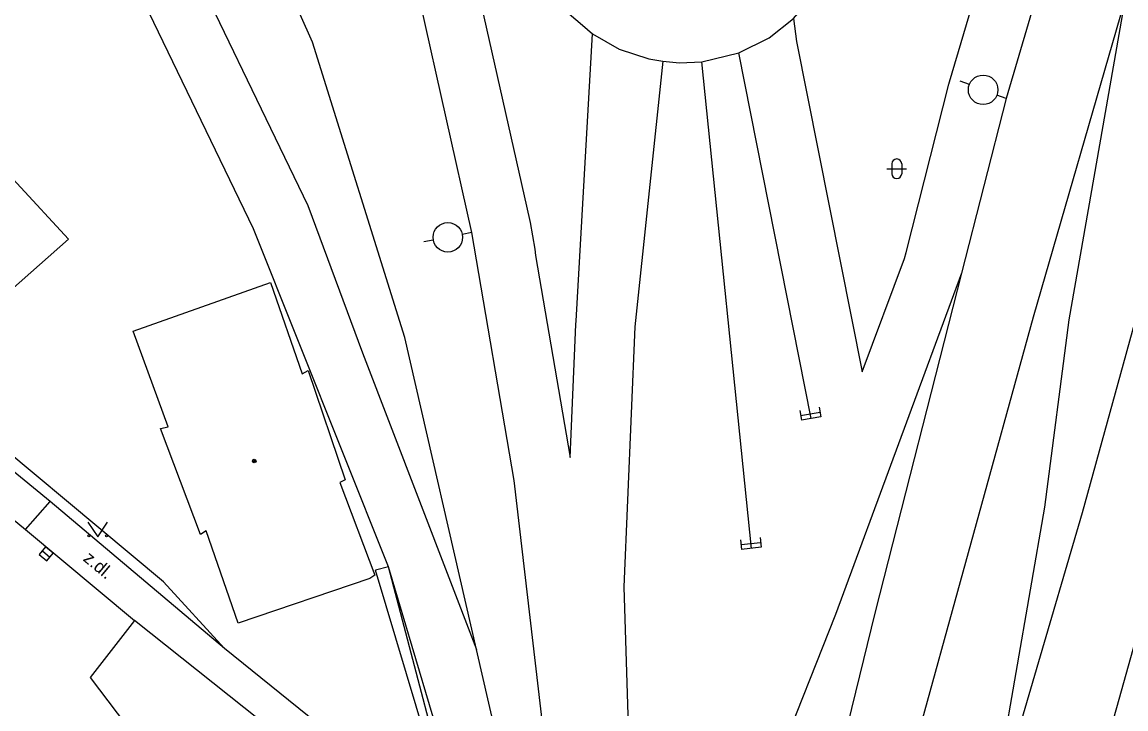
# Model space of a CAD drawing. Extents: x -598932 to -598196, y -1162207 to -1161504.
# Drawn here: x -598384.6 to -598328.5, y -1161967.1 to -1161932.2 of the extents above; entities that cross this region are included whole.
import ezdxf

# ---------------------------------------------------------------- set-up
doc = ezdxf.new("R2010")
doc.units = 0
for name, color, linetype in [('Level 12', 7, 'Continuous'), ('Level 27', 7, 'Continuous'), ('Level 36', 7, 'Continuous'), ('Level 39', 7, 'Continuous'), ('TM - budovy zdene_ betonove - VP', 7, 'Continuous'), ('TM - CD - osa koleji', 7, 'Continuous'), ('TM - chodniky - VP', 7, 'Continuous'), ('TM - komunikace - VP', 7, 'Continuous'), ('TM - letecke snimky - pomocna linie', 7, 'Continuous'), ('TM - plot zdeny_ ohradni zed - VP', 7, 'Continuous'), ('TM - popis povrchu', 7, 'Continuous'), ('TM - rozhrani mezi zpev. plochami mezi sebou - VP', 7, 'Continuous'), ('TM - rozhrani ploch obecne - VP', 7, 'Continuous')]:
    doc.layers.add(name, color=color, linetype=linetype)

msp = doc.modelspace()

# ---------------------------------------------------------------- linework, layer by layer
at = {"layer": 'Level 12'}
for p, q in [((-598336.446, -1161935.361), (-598336.913, -1161935.182)), ((-598334.58, -1161936.08), (-598335.047, -1161935.9)), ((-598361.74, -1161942.89), (-598362.231, -1161942.986)), ((-598363.703, -1161943.273), (-598364.194, -1161943.369)), ((-598345.066, -1161951.94), (-598344.983, -1161952.433)), ((-598345.025, -1161952.187), (-598344.039, -1161952.02)), ((-598344.08, -1161951.774), (-598343.997, -1161952.267)), ((-598343.997, -1161952.267), (-598344.983, -1161952.433)), ((-598348.084, -1161958.51), (-598348.027, -1161959.007)), ((-598348.055, -1161958.759), (-598347.062, -1161958.645)), ((-598347.033, -1161958.893), (-598348.027, -1161959.007)), ((-598347.09, -1161958.396), (-598347.033, -1161958.893))]:
    msp.add_line(p, q, dxfattribs=at)
for centre in [(-598335.747, -1161935.631), (-598362.967, -1161943.13)]:
    msp.add_circle(centre, 0.75, dxfattribs=at)
at = {"layer": 'Level 27'}
msp.add_line((-598383.583, -1161959.071), (-598383.197, -1161959.389), dxfattribs=at)
msp.add_lwpolyline([(-598383.742, -1161959.263), (-598383.357, -1161959.582), (-598383.038, -1161959.197), (-598383.423, -1161958.878)], close=True, dxfattribs=at)
at = {"layer": 'Level 36'}
for p, q in [((-598340.636, -1161939.646), (-598339.636, -1161939.646)), ((-598340.386, -1161939.396), (-598340.386, -1161939.896)), ((-598339.886, -1161939.396), (-598339.886, -1161939.896))]:
    msp.add_line(p, q, dxfattribs=at)
msp.add_lwpolyline([(-598381.27, -1161957.61), (-598380.77, -1161958.36), (-598380.27, -1161957.61)], dxfattribs=at)
for centre in [(-598381.22, -1161958.31), (-598380.321, -1161958.31)]:
    msp.add_circle(centre, 0.05, dxfattribs=at)
for centre, start, end in [((-598340.136, -1161939.396), 0, 180), ((-598340.136, -1161939.896), 180, 0)]:
    msp.add_arc(centre, 0.25, start, end, dxfattribs=at)
at = {"layer": 'Level 39'}
for radius in [0.09, 0.0398]:
    msp.add_circle((-598372.81, -1161954.51), radius, dxfattribs=at)
at = {"layer": 'TM - budovy zdene_ betonove - VP'}
for points in [[(-598387.52, -1161937.53), (-598382.26, -1161943.22)], [(-598382.26, -1161943.22), (-598389.64, -1161949.76)], [(-598378.97, -1161947.9), (-598371.98, -1161945.43)], [(-598371.98, -1161945.43), (-598370.38, -1161950.07)], [(-598377.19, -1161952.77), (-598378.97, -1161947.9)], [(-598370.38, -1161950.07), (-598370.06, -1161949.9)], [(-598370.06, -1161949.9), (-598368.18, -1161955.46)], [(-598377.57, -1161952.85), (-598377.19, -1161952.77)], [(-598375.55, -1161958.25), (-598377.57, -1161952.85)], [(-598368.18, -1161955.46), (-598368.46, -1161955.6)], [(-598368.46, -1161955.6), (-598366.68, -1161960.32)], [(-598375.25, -1161958.06), (-598375.55, -1161958.25)], [(-598373.63, -1161962.75), (-598375.25, -1161958.06)], [(-598366.94, -1161960.48), (-598373.63, -1161962.75)], [(-598366.68, -1161960.32), (-598366.94, -1161960.48)]]:
    msp.add_lwpolyline(points, dxfattribs=at)
at = {"layer": 'TM - CD - osa koleji'}
for points in [[(-598357.12, -1161977.93), (-598357.69, -1161971.76), (-598359.59, -1161955.49), (-598361.74, -1161942.89), (-598364.36, -1161931.22), (-598367.93, -1161915.3), (-598369.9, -1161906.65), (-598373.89, -1161889.05), (-598376.8, -1161873.73), (-598378.32, -1161860.94), (-598378.07, -1161843.25), (-598377.06, -1161830.11), (-598374.53, -1161806.47), (-598368.34, -1161750.33)], [(-598330.7, -1161957.12), (-598323.25, -1161930.13), (-598318.14, -1161914.72), (-598309.03, -1161890.52), (-598298.97, -1161868.44), (-598286, -1161841.52), (-598259.79, -1161788.26), (-598258.34, -1161785.34)], [(-598253.85, -1161787.55), (-598277.35, -1161835.24), (-598288.92, -1161858.05), (-598298.17, -1161877.98), (-598306.86, -1161898.82), (-598315.14, -1161920.44), (-598321.21, -1161940.59), (-598327.42, -1161961.55), (-598336.66, -1161994.53)], [(-598358.6, -1161976.73), (-598359.33, -1161973.53), (-598361.51, -1161964.09), (-598365.16, -1161948.23), (-598369.84, -1161933.2), (-598376.68, -1161917.87), (-598383.52, -1161906), (-598391.62, -1161893.76), (-598407.56, -1161871.85), (-598439.71, -1161827.1)], [(-598443.51, -1161830.07), (-598393.48, -1161900.03), (-598385.66, -1161911.94), (-598377.18, -1161926.79), (-598370.08, -1161941.52), (-598367.3, -1161949), (-598361.51, -1161964.09)], [(-598344.63, -1161988.07), (-598339.52, -1161970.16), (-598333.18, -1161947.17), (-598328.56, -1161931.17), (-598325.59, -1161920.89), (-598322.72, -1161911.41)], [(-598327.42, -1161911.8), (-598331.69, -1161926.28), (-598334.58, -1161936.08), (-598336.84, -1161944.95), (-598341.23, -1161962.18)], [(-598328.56, -1161931.17), (-598331.39, -1161947.33), (-598332.63, -1161956.86)], [(-598352.04, -1161934.18), (-598353.46, -1161947.69), (-598354.02, -1161960.9), (-598353.6, -1161974.49), (-598353.52, -1161980.85)], [(-598347.53, -1161958.95), (-598350.05, -1161934.2)], [(-598344.49, -1161952.35), (-598348.17, -1161933.75)], [(-598336.84, -1161944.95), (-598343.26, -1161962.31), (-598349.19, -1161977.3)], [(-598340.66, -1161991.29), (-598335.54, -1161973.67), (-598330.7, -1161957.12)], [(-598332.63, -1161956.86), (-598335.54, -1161973.67), (-598338.76, -1161992.83)], [(-598341.23, -1161962.18), (-598345.04, -1161977.69), (-598346.87, -1161986.25)]]:
    msp.add_lwpolyline(points, dxfattribs=at)
at = {"layer": 'TM - chodniky - VP'}
for points in [[(-598383.18, -1161956.56), (-598389.24, -1161951.61), (-598388.84, -1161951.12)], [(-598374.33, -1161964.05), (-598383.18, -1161956.56)], [(-598372.08, -1161978.94), (-598362.72, -1161975.49), (-598362.959, -1161975.299), (-598378.9, -1161962.61)]]:
    msp.add_lwpolyline(points, dxfattribs=at)
at = {"layer": 'TM - komunikace - VP'}
for points in [[(-598397.6, -1161947.15), (-598384.44, -1161957.99)], [(-598384.44, -1161957.99), (-598378.9, -1161962.61)], [(-598378.9, -1161962.61), (-598381.15, -1161965.52)], [(-598381.15, -1161965.52), (-598378.88, -1161968.52), (-598377.41, -1161970.94), (-598376.54, -1161972.52), (-598374.95, -1161975.07), (-598373.56, -1161977.04), (-598372.08, -1161978.94)]]:
    msp.add_lwpolyline(points, dxfattribs=at)
at = {"layer": 'TM - letecke snimky - pomocna linie'}
for points in [[(-598358.5, -1161739.6), (-598360.13, -1161751.92), (-598365.72, -1161802.62), (-598368.75, -1161829.91), (-598369.16, -1161834.56), (-598370.51, -1161850.29), (-598370.51, -1161867.69), (-598369, -1161887.95), (-598366.97, -1161905.98), (-598366.91, -1161906.31), (-598365, -1161914.64), (-598361.52, -1161930.21), (-598361.44, -1161930.56), (-598361.4, -1161930.7), (-598358.81, -1161942.23), (-598358.78, -1161942.38), (-598358.55, -1161943.74), (-598358.5, -1161944.06), (-598356.74, -1161954.33), (-598356.46, -1161947.56), (-598356.44, -1161947.38), (-598355.61, -1161932.79)], [(-598345.39, -1161932), (-598345.23, -1161933.17), (-598341.9, -1161949.98), (-598339.75, -1161944.21), (-598339.66, -1161943.91), (-598337.49, -1161935.34), (-598337.46, -1161935.23), (-598334.67, -1161925.84), (-598334.58, -1161925.43), (-598332.32, -1161909.94), (-598332.3, -1161909.85), (-598330.27, -1161898.83), (-598330.22, -1161898.47), (-598329.83, -1161891.84), (-598329.69, -1161889.41), (-598329.17, -1161880.36), (-598328.79, -1161864.7), (-598328.78, -1161864.55), (-598327.89, -1161852.55), (-598327.88, -1161852.43), (-598323.84, -1161817.24), (-598322.85, -1161808.11), (-598322.82, -1161807.86), (-598319.23, -1161762.27)], [(-598365.98, -1161959.89), (-598372.84, -1161942.7), (-598379.84, -1161928.19), (-598388.22, -1161913.51), (-598395.95, -1161901.73), (-598401.88, -1161893.44), (-598433.5, -1161849.22), (-598433.36, -1161849.42), (-598434.44, -1161847.92), (-598445.72, -1161833.26), (-598448.77, -1161829.32)]]:
    msp.add_lwpolyline(points, dxfattribs=at)
at = {"layer": 'TM - plot zdeny_ ohradni zed - VP'}
for points in [[(-598374.33, -1161964.05), (-598377.42, -1161960.65), (-598388.84, -1161951.12)], [(-598363.5, -1161972.77), (-598374.33, -1161964.05)]]:
    msp.add_lwpolyline(points, dxfattribs=at)
at = {"layer": 'TM - rozhrani mezi zpev. plochami mezi sebou - VP'}
msp.add_lwpolyline([(-598384.44, -1161957.99), (-598383.18, -1161956.56)], dxfattribs=at)
at = {"layer": 'TM - rozhrani ploch obecne - VP'}
for points in [[(-598348.17, -1161933.75), (-598346.63, -1161932.98), (-598345.39, -1161932), (-598344.38, -1161930.81), (-598343.61, -1161929.43), (-598343.12, -1161927.94), (-598342.93, -1161926.38), (-598343.05, -1161924.81), (-598343.48, -1161923.3), (-598344.19, -1161921.89), (-598345.16, -1161920.65), (-598346.35, -1161919.63), (-598347.71, -1161918.85), (-598348.32, -1161918.61), (-598349.21, -1161918.36), (-598350.29, -1161918.19), (-598351.3, -1161918.12), (-598352.19, -1161918.25), (-598353.83, -1161918.68)], [(-598353.83, -1161918.68), (-598355.33, -1161919.43), (-598356.56, -1161920.41), (-598357.58, -1161921.61), (-598358.35, -1161922.98), (-598358.84, -1161924.47), (-598359.02, -1161926.03), (-598358.91, -1161927.6), (-598358.48, -1161929.12), (-598357.77, -1161930.52), (-598356.8, -1161931.76), (-598356.12, -1161932.35), (-598355.61, -1161932.79), (-598354.25, -1161933.56), (-598352.75, -1161934.06), (-598352.04, -1161934.18), (-598351.19, -1161934.25), (-598350.05, -1161934.2), (-598348.17, -1161933.75)], [(-598365.98, -1161959.89), (-598366.64, -1161960.06)], [(-598363.51, -1161969.32), (-598365.98, -1161959.89)], [(-598363.51, -1161969.32), (-598363.2, -1161969.24), (-598365.98, -1161959.89)], [(-598363.54, -1161972.67), (-598364.49, -1161968.91), (-598364.04, -1161968.78), (-598366.64, -1161960.06)]]:
    msp.add_lwpolyline(points, dxfattribs=at)

# ---------------------------------------------------------------- texts
at = {"layer": 'TM - popis povrchu'}
msp.add_text('z.dl.', height=0.65, rotation=320.17, dxfattribs=at).set_placement((-598381.55, -1161959.54))

doc.saveas('drawing.dxf')
